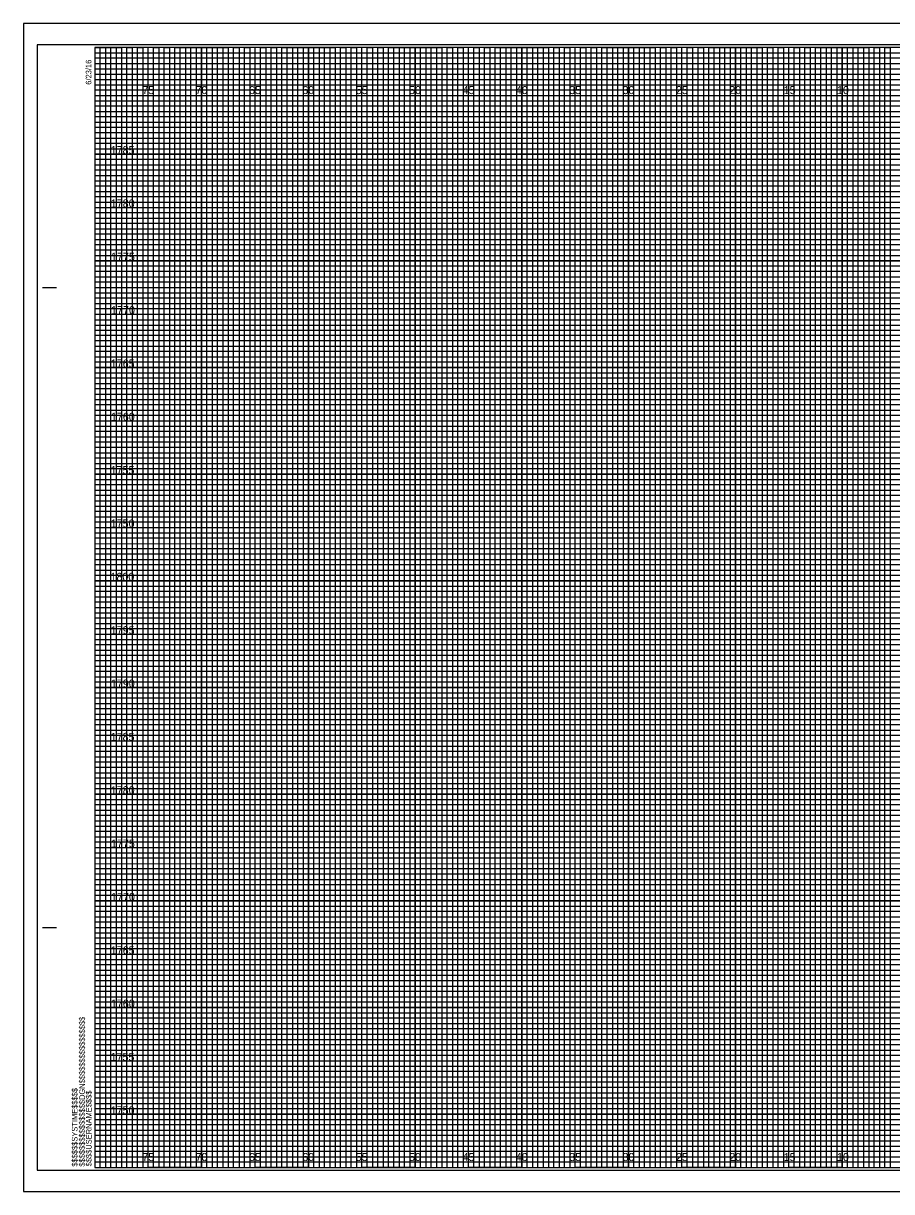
# Model space of a CAD drawing. Extents: x -7 to 162, y -2 to 767.
# Drawn here: x -6.7 to 74.6, y 657.8 to 767.2 of the extents above; entities that cross this region are included whole.
import ezdxf

# ---------------------------------------------------------------- set-up
doc = ezdxf.new("R2010")
doc.units = 0
for name, color, linetype in [('Prop Grid Mask', 7, 'Continuous'), ('Prop XS Elevation Labels', 7, 'Continuous'), ('Sheet Cross Section CELL', 7, 'Continuous'), ('Sheet Cross Section Grid Major CELL', 7, 'Continuous'), ('Sheet Cross Section Grid Middle CELL', 7, 'Continuous'), ('Sheet Cross Section Grid Minor 1 CELL', 7, 'Continuous'), ('Sheet Cross Section Grid Minor 2 CELL', 7, 'Continuous'), ('Sheet Cutting Line CELL', 7, 'Continuous'), ('Sheet DOT Grid CELL', 7, 'Continuous'), ('Sheet Plot Border Inside CELL', 7, 'Continuous'), ('Sheet Plot Border Outside CELL', 7, 'Continuous')]:
    doc.layers.add(name, color=color, linetype=linetype)

msp = doc.modelspace()

# ---------------------------------------------------------------- linework, layer by layer
at = {"layer": 'Sheet Cross Section CELL'}
for p, q in [((-4.9, 742.5), (-3.65, 742.5)), ((-4.85, 742.5), (-3.6, 742.5)), ((-4.9, 682.5), (-3.65, 682.5)), ((-4.85, 682.5), (-3.6, 682.5)), ((0, 660), (0, 660)), ((0, 660), (0, 660)), ((0, 660), (0, 660)), ((0, 660), (0, 660)), ((0, 660), (0, 660)), ((0, 660), (0, 660)), ((0, 660), (0, 660))]:
    msp.add_line(p, q, dxfattribs=at)
msp.add_lwpolyline([(160, 765), (0, 765), (0, 660), (160, 660)], close=True, dxfattribs=at)
at = {"layer": 'Sheet Cross Section Grid Major CELL'}
for p, q in [((5, 765), (0, 765)), ((5, 660), (5, 765)), ((15, 765), (10, 765)), ((10, 765), (10, 660)), ((15, 660), (15, 765)), ((25, 765), (20, 765)), ((20, 765), (20, 660)), ((25, 660), (25, 765)), ((35, 765), (30, 765)), ((30, 765), (30, 660)), ((35, 660), (35, 765)), ((45, 765), (40, 765)), ((40, 765), (40, 660)), ((45, 660), (45, 765)), ((55, 765), (50, 765)), ((50, 765), (50, 660)), ((55, 660), (55, 765)), ((65, 765), (60, 765)), ((60, 765), (60, 660)), ((65, 660), (65, 765)), ((75, 765), (70, 765)), ((70, 765), (70, 660)), ((10, 660), (5, 660)), ((20, 660), (15, 660)), ((30, 660), (25, 660)), ((40, 660), (35, 660)), ((50, 660), (45, 660)), ((60, 660), (55, 660)), ((70, 660), (65, 660))]:
    msp.add_line(p, q, dxfattribs=at)
for points in [[(0, 760), (160, 760), (160, 755), (0, 755)], [(0, 750), (160, 750), (160, 745), (0, 745)], [(0, 740), (160, 740), (160, 735), (0, 735)], [(0, 730), (160, 730), (160, 725), (0, 725)], [(0, 720), (160, 720), (160, 715), (0, 715)], [(0, 710), (160, 710), (160, 705), (0, 705)], [(0, 700), (160, 700), (160, 695), (0, 695)], [(0, 690), (160, 690), (160, 685), (0, 685)], [(0, 680), (160, 680), (160, 675), (0, 675)], [(0, 670), (160, 670), (160, 665), (0, 665)]]:
    msp.add_lwpolyline(points, dxfattribs=at)
at = {"layer": 'Sheet Cross Section Grid Middle CELL'}
for points in [[(0, 765), (2.5, 765), (2.5, 660), (7.5, 660), (7.5, 765), (12.5, 765), (12.5, 660), (17.5, 660), (17.5, 765), (22.5, 765), (22.5, 660), (27.5, 660), (27.5, 765), (32.5, 765), (32.5, 660), (37.5, 660), (37.5, 765), (42.5, 765), (42.5, 660), (47.5, 660), (47.5, 765), (52.5, 765), (52.5, 660), (57.5, 660), (57.5, 765), (62.5, 765), (62.5, 660), (67.5, 660), (67.5, 765), (72.5, 765), (72.5, 660), (77.5, 660)], [(0, 762.5), (137.5, 762.5)], [(0, 752.5), (160, 752.5), (160, 757.5), (0, 757.5)], [(0, 742.5), (160, 742.5), (160, 747.5), (0, 747.5)], [(0, 732.5), (160, 732.5), (160, 737.5), (0, 737.5)], [(0, 722.5), (160, 722.5), (160, 727.5), (0, 727.5)], [(0, 712.5), (160, 712.5), (160, 717.5), (0, 717.5)], [(0, 702.5), (160, 702.5), (160, 707.5), (0, 707.5)], [(0, 692.5), (160, 692.5), (160, 697.5), (0, 697.5)], [(0, 682.5), (160, 682.5), (160, 687.5), (0, 687.5)], [(0, 672.5), (160, 672.5), (160, 677.5), (0, 677.5)], [(0, 662.5), (160, 662.5), (160, 667.5), (0, 667.5)]]:
    msp.add_lwpolyline(points, dxfattribs=at)
at = {"layer": 'Sheet Cross Section Grid Minor 1 CELL'}
for p, q in [((0, 764.5), (130, 764.5)), ((130, 763.99), (0, 763.99)), ((0, 763.99), (0, 763.5)), ((0, 763.5), (130, 763.5)), ((130, 762.95), (0, 762.95)), ((0, 762.95), (0, 762)), ((0, 762), (160, 762))]:
    msp.add_line(p, q, dxfattribs=at)
for points in [[(0, 761.5), (135, 761.5), (160, 761.5), (160, 761), (0, 761)], [(0, 760.5), (160, 760.5), (160, 759.5), (0, 759.5)], [(0, 759), (160, 759), (160, 758.5), (0, 758.49)], [(0, 758), (160, 758), (160, 757), (0, 757)], [(0, 756.5), (160, 756.5), (160, 756), (0, 756)], [(0, 755.5), (160, 755.5), (160, 754.5), (0, 754.5)], [(0, 754), (160, 754), (160, 753.5), (0, 753.5)], [(0, 753), (160, 753), (160, 752), (0, 752)], [(0, 751.5), (160, 751.5), (160, 751), (0, 751)], [(0, 750.5), (160, 750.5), (160, 749.5), (0, 749.5)], [(0, 749), (160, 749), (160, 748.5), (0, 748.5)], [(0, 748), (160, 748), (160, 746.98), (160, 746.5), (160, 746), (0, 746)], [(0, 747), (160, 747), (160, 746.5), (0, 746.5)], [(0, 745.5), (160, 745.5), (160, 744.5), (0, 744.51)], [(0, 744.51), (160, 744.5), (160, 744), (0, 744)], [(0, 743.5), (160, 743.5), (160, 743), (0, 743)], [(0, 742), (160, 742), (160, 741.5), (0, 741.5)], [(0, 741), (160, 741), (160, 740.5), (0, 740.5)], [(-0.04, 739.45), (160, 739.45), (160, 738.94), (-0.04, 738.94)], [(0, 738.5), (160, 738.5), (160, 738), (0, 738)], [(0, 737), (160, 737), (160, 736.5), (0, 736.5)], [(0, 736), (160, 736), (160, 735.5), (0, 735.5)], [(0, 734.5), (160, 734.5), (160, 734), (0, 734)], [(0, 733.5), (160, 733.5), (160, 733), (0, 733)], [(0, 732), (160, 732), (160, 731.5), (0, 731.5)], [(0, 731), (160, 731), (160, 730.5), (0, 730.5)], [(0, 729.5), (160, 729.5), (160, 728.99), (0, 729)], [(0, 728.5), (160, 728.5), (160, 728), (0, 728)], [(0, 727), (160, 727), (160, 726.5), (0, 726.5)], [(0, 726), (160, 726), (160, 725.5), (0, 725.5)], [(0, 724.5), (160, 724.5), (160, 724), (0, 724)], [(0, 723.5), (160, 723.5), (160, 723), (0, 723)], [(0, 722), (160, 722), (160, 721.5), (0, 721.5)], [(0, 721), (160, 721), (160, 720.5), (0, 720.5)], [(0, 719.5), (160, 719.5), (160, 719), (0, 719)], [(0, 718.5), (160.03, 718.46), (160, 718), (0, 718)], [(0, 717), (160, 717), (160, 716.5), (0, 716.5)], [(0, 716), (160, 716), (160, 715.5), (0, 715.5)], [(0, 714.5), (160, 714.5), (160, 714), (0, 714)], [(0, 713.5), (160, 713.5), (160, 713), (0, 713)], [(0, 712), (160, 712), (160, 711.5), (0, 711.5)], [(0, 711), (160, 711), (160, 710.5), (0, 710.5)], [(0, 709.5), (160, 709.5), (160, 709), (0, 709)], [(0, 708.5), (160, 708.5), (160, 708), (0, 708)], [(0, 707), (160, 707), (160, 706.5), (0, 706.5)], [(0, 706), (160, 706), (160, 705.5), (0, 705.5)], [(0, 704.5), (160, 704.5), (160, 704), (0, 704)], [(0, 703.5), (160, 703.5), (160, 703), (0, 703)], [(0, 702), (160, 702), (160, 701.5), (0, 701.5)], [(0, 701), (160, 701), (160, 700.5), (0, 700.5)], [(0, 699.5), (160, 699.5), (160, 698.99), (0, 699)], [(0, 698.5), (160, 698.5), (160, 698), (0, 698)], [(0, 697), (160, 697), (160, 696.5), (0, 696.5)], [(0, 696), (160, 696), (160, 695.5), (0, 695.5)], [(0, 694.5), (160, 694.5), (160, 694), (0, 694)], [(0, 693.5), (160, 693.5), (160, 693), (0, 693)], [(0, 692), (160, 692), (160, 691.5), (0, 691.5)], [(0, 691), (160, 691), (160, 690.5), (0, 690.5)], [(0, 689.5), (160, 689.5), (160, 689), (0, 689)], [(0, 688.5), (160.03, 688.46), (160, 688), (0, 688)], [(0, 687), (160, 687), (160, 686.5), (0, 686.5)], [(0, 686), (160, 686), (160, 685.5), (0, 685.5)], [(0, 684.5), (160, 684.5), (160, 684), (0, 684)], [(0, 683.5), (160, 683.5), (160, 683), (0, 683)], [(0, 682), (160, 682), (160, 681.5), (0, 681.5)], [(0, 681), (160, 681), (160, 680.5), (0, 680.5)], [(0, 679.5), (160, 679.5), (160, 679), (0, 679)], [(0, 678.5), (160, 678.5), (160, 678), (0, 678)], [(0, 677), (160, 677), (160, 676.5), (0, 676.5)], [(0, 676), (160, 676), (160, 675.5), (0, 675.5)], [(0, 674.5), (160, 674.5), (160, 674), (0, 674)], [(0, 673.5), (160, 673.5), (160, 673), (0, 673)], [(0, 672), (160, 672), (160, 671.5), (0, 671.5)], [(0, 671), (160, 671), (160, 670.5), (0, 670.5)], [(0, 669.5), (160, 669.5), (160, 669), (0, 669)], [(0, 668.5), (160, 668.5), (160, 668), (0, 668)], [(0, 667), (160, 667), (160, 666.5), (0, 666.5)], [(0, 666), (160, 666), (160, 665.5), (0, 665.5)], [(0, 664.5), (160, 664.5), (160, 664), (0, 664)], [(0, 663.5), (160, 663.5), (160, 663), (0, 663)], [(0, 662), (160, 662), (160, 661.5), (0, 661.5)], [(0, 661), (160, 661), (160, 660.5), (0, 660.5)]]:
    msp.add_lwpolyline(points, dxfattribs=at)
at = {"layer": 'Sheet Cross Section Grid Minor 2 CELL'}
for points in [[(0, 660), (0.5, 660), (0.5, 765), (1, 765), (1, 660)], [(1, 660), (1.5, 660), (1.5, 765), (2, 765), (2, 660)], [(2.5, 660), (3, 660), (3, 765), (3.5, 765), (3.5, 660)], [(3.5, 660), (4, 660), (4, 765), (4.5, 765), (4.5, 660)], [(5, 660), (5.5, 660), (5.5, 765), (6, 765), (6, 660)], [(6, 660), (6.5, 660), (6.5, 765), (7, 765), (7, 660)], [(7.5, 660), (8, 660), (8, 765), (8.5, 765), (8.5, 660)], [(8.5, 660), (9, 660), (9, 765), (9.5, 765), (9.5, 660)], [(10, 660), (10.5, 660), (10.5, 765), (11, 765), (11, 660)], [(11, 660), (11.5, 660), (11.5, 765), (12, 765), (12, 660)], [(12.5, 660), (13, 660), (13, 765), (13.5, 765), (13.5, 660)], [(13.5, 660), (14, 660), (14, 765), (14.5, 765), (14.5, 660)], [(15, 660), (15.5, 660), (15.5, 765), (16, 765), (16, 660)], [(16, 660), (16.5, 660), (16.5, 765), (17, 765), (17, 660)], [(17.5, 660), (18, 660), (18, 765), (18.5, 765), (18.5, 660)], [(18.5, 660), (19, 660), (19, 765), (19.5, 765), (19.5, 660)], [(20, 660), (20.5, 660), (20.5, 765), (21, 765), (21, 660)], [(21, 660), (21.5, 660), (21.5, 765), (22, 765), (22, 660)], [(22.5, 660), (23, 660), (23, 765), (23.5, 765), (23.5, 660)], [(23.5, 660), (24, 660), (24, 765), (24.5, 765), (24.5, 660)], [(25, 660), (25.5, 660), (25.5, 765), (26, 765), (26, 660)], [(26, 660), (26.5, 660), (26.5, 765), (27, 765), (27, 660)], [(27.5, 660), (28, 660), (28, 765), (28.5, 765), (28.5, 660)], [(28.5, 660), (29, 660), (29, 765), (29.5, 765), (29.5, 660)], [(30, 660), (30.5, 660), (30.5, 765), (31, 765), (31, 660)], [(31, 660), (31.5, 660), (31.5, 765), (32, 765), (32, 660)], [(32.5, 660), (33, 660), (33, 765), (33.5, 765), (33.5, 660)], [(33.5, 660), (34, 660), (34, 765), (34.5, 765), (34.5, 660)], [(35, 660), (35.5, 660), (35.5, 765), (36, 765), (36, 660)], [(36, 660), (36.5, 660), (36.5, 765), (37, 765), (37, 660)], [(37.5, 660), (38, 660), (38, 765), (38.5, 765), (38.5, 660)], [(38.5, 660), (39, 660), (39, 765), (39.5, 765), (39.5, 660)], [(40, 660), (40.5, 660), (40.5, 765), (41, 765), (41, 660)], [(41, 660), (41.5, 660), (41.5, 765), (42, 765), (42, 660)], [(42.5, 660), (43, 660), (43, 765), (43.5, 765), (43.5, 660)], [(43.5, 660), (44, 660), (44, 765), (44.5, 765), (44.5, 660)], [(45, 660), (45.5, 660), (45.5, 765), (46, 765), (46, 660)], [(46, 660), (46.5, 660), (46.5, 765), (47, 765), (47, 660)], [(47.5, 660), (48, 660), (48, 765), (48.5, 765), (48.5, 660)], [(48.5, 660), (49, 660), (49, 765), (49.5, 765), (49.5, 660)], [(50, 660), (50.5, 660), (50.5, 765), (51, 765), (51, 660)], [(51, 660), (51.5, 660), (51.5, 765), (52, 765), (52, 660)], [(52.5, 660), (53, 660), (53, 765), (53.5, 765), (53.5, 660)], [(53.5, 660), (54, 660), (54, 765), (54.5, 765), (54.5, 660)], [(55, 660), (55.5, 660), (55.5, 765), (56, 765), (56, 660)], [(56, 660), (56.5, 660), (56.5, 765), (57, 765), (57, 660)], [(57.5, 660), (58, 660), (58, 765), (58.5, 765), (58.5, 660)], [(58.5, 660), (59, 660), (59, 765), (59.5, 765), (59.5, 660)], [(60, 660), (60.5, 660), (60.5, 765), (61, 765), (61, 660)], [(61, 660), (61.5, 660), (61.5, 765), (62, 765), (62, 660)], [(62.5, 660), (63, 660), (63, 765), (63.5, 765), (63.5, 660)], [(63.5, 660), (64, 660), (64, 765), (64.5, 765), (64.5, 660)], [(65, 660), (65.5, 660), (65.5, 765), (66, 765), (66, 660)], [(66, 660), (66.5, 660), (66.5, 765), (67, 765), (67, 660)], [(67.5, 660), (68, 660), (68, 765), (68.5, 765), (68.5, 660)], [(68.5, 660), (69, 660), (69, 765), (69.5, 765), (69.5, 660)], [(70, 660), (70.5, 660), (70.5, 765), (71, 765), (71, 660)], [(71, 660), (71.5, 660), (71.5, 765), (72, 765), (72, 660)], [(72.5, 660), (73, 660), (73, 765), (73.5, 765), (73.5, 660)], [(73.5, 660), (74, 660), (74, 765), (74.5, 765), (74.5, 660)]]:
    msp.add_lwpolyline(points, dxfattribs=at)
at = {"layer": 'Sheet Cutting Line CELL'}
for p, q in [((161.65, 767.25), (-6.7, 767.25)), ((-6.7, 767.25), (-6.7, 657.75)), ((-6.7, 657.75), (161.65, 657.75))]:
    msp.add_line(p, q, dxfattribs=at)
at = {"layer": 'Sheet DOT Grid CELL'}
for p, q in [((5, 660), (5, 765)), ((10, 660), (10, 765)), ((15, 660), (15, 765)), ((20, 660), (20, 765)), ((25, 660), (25, 765)), ((30, 660), (30, 765)), ((35, 660), (35, 765)), ((40, 660), (40, 765)), ((45, 660), (45, 765)), ((50, 660), (50, 765)), ((55, 660), (55, 765)), ((60, 660), (60, 765)), ((65, 660), (65, 765)), ((70, 660), (70, 765)), ((0, 760), (160, 760)), ((0, 755), (160, 755)), ((0, 750), (160, 750)), ((0, 745), (160, 745)), ((0, 740), (160, 740)), ((0, 735), (160, 735)), ((0, 730), (160, 730)), ((0, 725), (160, 725)), ((0, 720), (160, 720)), ((0, 715), (160, 715)), ((0, 710), (160, 710)), ((0, 705), (160, 705)), ((0, 700), (160, 700)), ((0, 695), (160, 695)), ((0, 690), (160, 690)), ((0, 685), (160, 685)), ((0, 680), (160, 680)), ((0, 675), (160, 675)), ((0, 670), (160, 670)), ((0, 665), (160, 665))]:
    msp.add_line(p, q, dxfattribs=at)
at = {"layer": 'Sheet Plot Border Inside CELL'}
msp.add_lwpolyline([(-5.4, 659.75), (161.2, 659.75), (161.2, 765.25), (-5.4, 765.25)], close=True, dxfattribs=at)
at = {"layer": 'Sheet Plot Border Outside CELL'}
msp.add_lwpolyline([(-6.7, 657.75), (161.65, 657.75), (161.65, 767.25), (-6.7, 767.25)], close=True, dxfattribs=at)

# ---------------------------------------------------------------- texts
at = {"layer": 'Prop Grid Mask'}
for s, p in [('75', (4.44, 760.62)), ('70', (9.43, 760.62)), ('65', (14.44, 760.62)), ('60', (19.43, 760.62)), ('55', (24.44, 760.62)), ('50', (29.43, 760.62)), ('45', (34.44, 760.62)), ('40', (39.43, 760.62)), ('35', (44.44, 760.62)), ('30', (49.43, 760.62)), ('25', (54.44, 760.62)), ('20', (59.43, 760.62)), ('15', (64.53, 760.62)), ('10', (69.52, 760.62)), ('70', (9.43, 660.62)), ('65', (14.44, 660.62)), ('60', (19.43, 660.62)), ('50', (29.43, 660.62)), ('40', (39.43, 660.62)), ('35', (44.44, 660.62)), ('30', (49.43, 660.62)), ('25', (54.44, 660.62)), ('20', (59.43, 660.62)), ('10', (69.52, 660.62)), ('75', (4.44, 660.62)), ('55', (24.44, 660.62)), ('45', (34.44, 660.62)), ('15', (64.53, 660.62))]:
    msp.add_text(s, height=0.75, dxfattribs=at).set_placement(p)
at = {"layer": 'Prop XS Elevation Labels'}
for s, p in [('1785', (1.48, 755)), ('1780', (1.49, 750)), ('1775', (1.51, 745)), ('1770', (1.52, 740)), ('1765', (1.49, 735)), ('1760', (1.5, 730)), ('1755', (1.47, 725)), ('1750', (1.48, 720)), ('1800', (1.46, 715)), ('1795', (1.49, 710)), ('1790', (1.5, 705)), ('1785', (1.48, 700)), ('1780', (1.49, 695)), ('1775', (1.51, 690)), ('1770', (1.52, 685)), ('1765', (1.49, 680)), ('1760', (1.5, 675)), ('1755', (1.47, 670)), ('1750', (1.48, 665))]:
    msp.add_text(s, height=0.75, dxfattribs=at).set_placement(p)
at = {"layer": 'Sheet Cross Section CELL'}
for s, p in [('6/23/16', (-0.33, 761.5)), ('$$$$$$$$$$$$$$$$DGN$$$$$$$$$$$$$$$$', (-0.94, 660.09)), ('$$$$$$SYSTIME$$$$$', (-1.63, 660.09)), ('$$$$USERNAME$$$$', (-0.31, 660.12))]:
    msp.add_text(s, height=0.525, rotation=90, dxfattribs=at).set_placement(p)

doc.saveas('drawing.dxf')
